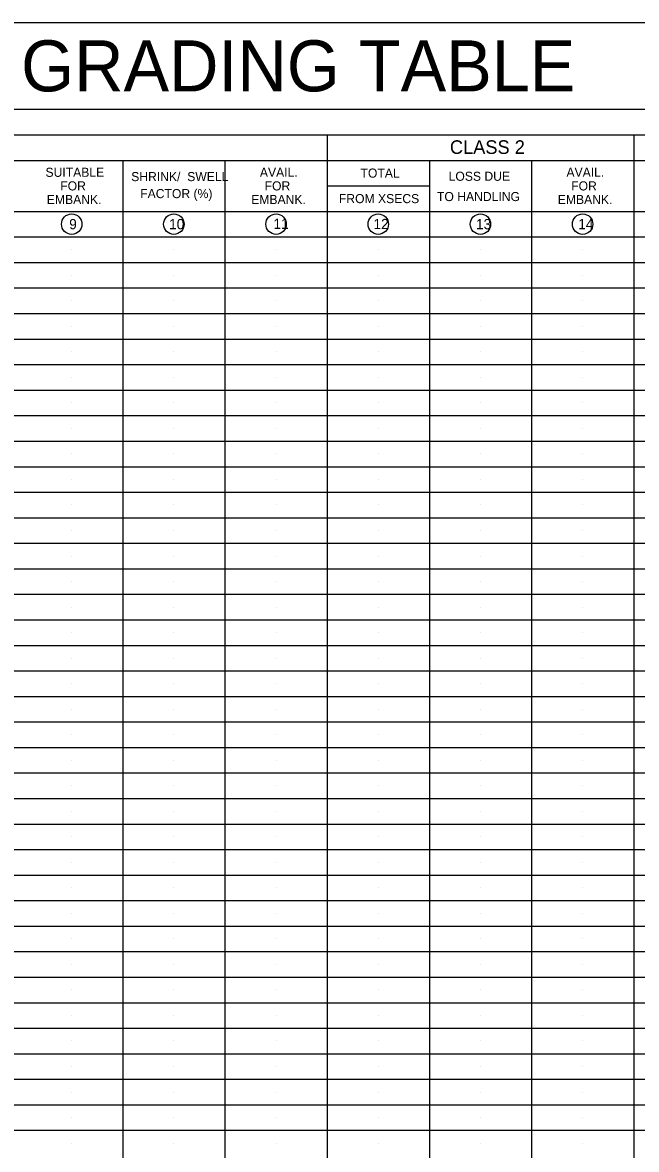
# Model space of a CAD drawing. Extents: x 1.3 to 38.6, y 0 to 21.1.
# Drawn here: x 9.92 to 15.32, y 11.12 to 21.05 of the extents above; entities that cross this region are included whole.
import ezdxf

# ---------------------------------------------------------------- set-up
doc = ezdxf.new("R2010")
doc.units = 0
for name, color, linetype in [('G-ANNO-TABL', 7, 'Continuous'), ('G-ANNO-TITL', 7, 'Continuous'), ('G-USER-LINE', 7, 'Continuous')]:
    doc.layers.add(name, color=color, linetype=linetype)

msp = doc.modelspace()

# ---------------------------------------------------------------- linework, layer by layer
at = {"layer": 'G-ANNO-TABL'}
for p, q in [((2.248, 21.055), (22.498, 21.055)), ((2.248, 20.29), (22.498, 20.29)), ((2.698, 20.065), (17.098, 20.065)), ((12.598, 20.0651), (12.598, 4.54)), ((15.298, 20.0651), (15.298, 4.54)), ((2.698, 19.84), (22.498, 19.84)), ((10.798, 19.8401), (10.798, 4.54)), ((11.698, 19.8401), (11.698, 4.54)), ((13.498, 19.8401), (13.498, 4.54)), ((14.398, 19.8401), (14.398, 4.54)), ((12.598, 19.615), (13.498, 19.615)), ((2.698, 19.39), (22.498, 19.39)), ((2.248, 19.165), (22.498, 19.165)), ((2.698, 18.94), (22.498, 18.94)), ((2.698, 18.715), (22.498, 18.715)), ((2.698, 18.49), (22.498, 18.49)), ((2.698, 18.265), (22.498, 18.265)), ((2.698, 18.04), (22.498, 18.04)), ((2.698, 17.815), (22.498, 17.815)), ((2.698, 17.59), (22.498, 17.59)), ((2.698, 17.365), (22.498, 17.365)), ((2.698, 17.14), (22.498, 17.14)), ((2.698, 16.915), (22.498, 16.915)), ((2.698, 16.69), (22.498, 16.69)), ((2.698, 16.465), (22.498, 16.465)), ((2.698, 16.24), (22.498, 16.24)), ((2.698, 16.015), (22.498, 16.015)), ((2.698, 15.79), (22.498, 15.79)), ((2.698, 15.565), (22.498, 15.565)), ((2.698, 15.34), (22.498, 15.34)), ((2.698, 15.115), (22.498, 15.115)), ((2.698, 14.89), (22.498, 14.89)), ((2.698, 14.665), (22.498, 14.665)), ((2.698, 14.44), (22.498, 14.44)), ((2.698, 14.215), (22.498, 14.215)), ((2.698, 13.99), (22.498, 13.99)), ((2.698, 13.765), (22.498, 13.765)), ((2.698, 13.54), (22.498, 13.54)), ((2.698, 13.315), (22.498, 13.315)), ((2.698, 13.09), (22.498, 13.09)), ((2.698, 12.865), (22.498, 12.865)), ((2.698, 12.64), (22.498, 12.64)), ((2.698, 12.415), (22.498, 12.415)), ((2.698, 12.19), (22.498, 12.19)), ((2.698, 11.965), (22.498, 11.965)), ((2.698, 11.74), (22.498, 11.74)), ((2.698, 11.515), (22.498, 11.515)), ((2.698, 11.29), (22.498, 11.29))]:
    msp.add_line(p, q, dxfattribs=at)
at = {"layer": 'G-ANNO-TITL'}
for centre in [(10.3479, 19.278), (11.2479, 19.278), (12.1479, 19.278), (13.0479, 19.278), (13.9479, 19.278), (14.8479, 19.278)]:
    msp.add_circle(centre, 0.09, dxfattribs=at)
at = {"layer": 'G-USER-LINE'}
for p, q in [((10.348, 19.2775), (10.348, 19.2775)), ((11.248, 19.2775), (11.248, 19.2775)), ((12.148, 19.2775), (12.148, 19.2775)), ((13.048, 19.2775), (13.048, 19.2775)), ((13.948, 19.2775), (13.948, 19.2775)), ((14.848, 19.2775), (14.848, 19.2775)), ((10.348, 19.0525), (10.348, 19.0525)), ((11.248, 19.0525), (11.248, 19.0525)), ((12.148, 19.0525), (12.148, 19.0525)), ((13.048, 19.0525), (13.048, 19.0525)), ((13.948, 19.0525), (13.948, 19.0525)), ((14.848, 19.0525), (14.848, 19.0525)), ((10.348, 18.8275), (10.348, 18.8275)), ((11.248, 18.8275), (11.248, 18.8275)), ((12.148, 18.8275), (12.148, 18.8275)), ((13.048, 18.8275), (13.048, 18.8275)), ((13.948, 18.8275), (13.948, 18.8275)), ((14.848, 18.8275), (14.848, 18.8275)), ((10.348, 18.6025), (10.348, 18.6025)), ((11.248, 18.6025), (11.248, 18.6025)), ((12.148, 18.6025), (12.148, 18.6025)), ((13.048, 18.6025), (13.048, 18.6025)), ((13.948, 18.6025), (13.948, 18.6025)), ((14.848, 18.6025), (14.848, 18.6025)), ((10.348, 18.3775), (10.348, 18.3775)), ((11.248, 18.3775), (11.248, 18.3775)), ((12.148, 18.3775), (12.148, 18.3775)), ((13.048, 18.3775), (13.048, 18.3775)), ((13.948, 18.3775), (13.948, 18.3775)), ((14.848, 18.3775), (14.848, 18.3775)), ((10.348, 18.1525), (10.348, 18.1525)), ((11.248, 18.1525), (11.248, 18.1525)), ((12.148, 18.1525), (12.148, 18.1525)), ((13.048, 18.1525), (13.048, 18.1525)), ((13.948, 18.1525), (13.948, 18.1525)), ((14.848, 18.1525), (14.848, 18.1525)), ((10.348, 17.9275), (10.348, 17.9275)), ((11.248, 17.9275), (11.248, 17.9275)), ((12.148, 17.9275), (12.148, 17.9275)), ((13.048, 17.9275), (13.048, 17.9275)), ((13.948, 17.9275), (13.948, 17.9275)), ((14.848, 17.9275), (14.848, 17.9275)), ((10.348, 17.7025), (10.348, 17.7025)), ((11.248, 17.7025), (11.248, 17.7025)), ((12.148, 17.7025), (12.148, 17.7025)), ((13.048, 17.7025), (13.048, 17.7025)), ((13.948, 17.7025), (13.948, 17.7025)), ((14.848, 17.7025), (14.848, 17.7025)), ((10.348, 17.4775), (10.348, 17.4775)), ((11.248, 17.4775), (11.248, 17.4775)), ((12.148, 17.4775), (12.148, 17.4775)), ((13.048, 17.4775), (13.048, 17.4775)), ((13.948, 17.4775), (13.948, 17.4775)), ((14.848, 17.4775), (14.848, 17.4775)), ((10.348, 17.2525), (10.348, 17.2525)), ((11.248, 17.2525), (11.248, 17.2525)), ((12.148, 17.2525), (12.148, 17.2525)), ((13.048, 17.2525), (13.048, 17.2525)), ((13.948, 17.2525), (13.948, 17.2525)), ((14.848, 17.2525), (14.848, 17.2525)), ((10.348, 17.0275), (10.348, 17.0275)), ((11.248, 17.0275), (11.248, 17.0275)), ((12.148, 17.0275), (12.148, 17.0275)), ((13.048, 17.0275), (13.048, 17.0275)), ((13.948, 17.0275), (13.948, 17.0275)), ((14.848, 17.0275), (14.848, 17.0275)), ((10.348, 16.8025), (10.348, 16.8025)), ((11.248, 16.8025), (11.248, 16.8025)), ((12.148, 16.8025), (12.148, 16.8025)), ((13.048, 16.8025), (13.048, 16.8025)), ((13.948, 16.8025), (13.948, 16.8025)), ((14.848, 16.8025), (14.848, 16.8025)), ((10.348, 16.5775), (10.348, 16.5775)), ((11.248, 16.5775), (11.248, 16.5775)), ((12.148, 16.5775), (12.148, 16.5775)), ((13.048, 16.5775), (13.048, 16.5775)), ((13.948, 16.5775), (13.948, 16.5775)), ((14.848, 16.5775), (14.848, 16.5775)), ((10.348, 16.3525), (10.348, 16.3525)), ((11.248, 16.3525), (11.248, 16.3525)), ((12.148, 16.3525), (12.148, 16.3525)), ((13.048, 16.3525), (13.048, 16.3525)), ((13.948, 16.3525), (13.948, 16.3525)), ((14.848, 16.3525), (14.848, 16.3525)), ((10.348, 16.1275), (10.348, 16.1275)), ((11.248, 16.1275), (11.248, 16.1275)), ((12.148, 16.1275), (12.148, 16.1275)), ((13.048, 16.1275), (13.048, 16.1275)), ((13.948, 16.1275), (13.948, 16.1275)), ((14.848, 16.1275), (14.848, 16.1275)), ((10.348, 15.9025), (10.348, 15.9025)), ((11.248, 15.9025), (11.248, 15.9025)), ((12.148, 15.9025), (12.148, 15.9025)), ((13.048, 15.9025), (13.048, 15.9025)), ((13.948, 15.9025), (13.948, 15.9025)), ((14.848, 15.9025), (14.848, 15.9025)), ((10.348, 15.6775), (10.348, 15.6775)), ((11.248, 15.6775), (11.248, 15.6775)), ((12.148, 15.6775), (12.148, 15.6775)), ((13.048, 15.6775), (13.048, 15.6775)), ((13.948, 15.6775), (13.948, 15.6775)), ((14.848, 15.6775), (14.848, 15.6775)), ((10.348, 15.4525), (10.348, 15.4525)), ((11.248, 15.4525), (11.248, 15.4525)), ((12.148, 15.4525), (12.148, 15.4525)), ((13.048, 15.4525), (13.048, 15.4525)), ((13.948, 15.4525), (13.948, 15.4525)), ((14.848, 15.4525), (14.848, 15.4525)), ((10.348, 15.2275), (10.348, 15.2275)), ((11.248, 15.2275), (11.248, 15.2275)), ((12.148, 15.2275), (12.148, 15.2275)), ((13.048, 15.2275), (13.048, 15.2275)), ((13.948, 15.2275), (13.948, 15.2275)), ((14.848, 15.2275), (14.848, 15.2275)), ((10.348, 15.0025), (10.348, 15.0025)), ((11.248, 15.0025), (11.248, 15.0025)), ((12.148, 15.0025), (12.148, 15.0025)), ((13.048, 15.0025), (13.048, 15.0025)), ((13.948, 15.0025), (13.948, 15.0025)), ((14.848, 15.0025), (14.848, 15.0025)), ((10.348, 14.7775), (10.348, 14.7775)), ((11.248, 14.7775), (11.248, 14.7775)), ((12.148, 14.7775), (12.148, 14.7775)), ((13.048, 14.7775), (13.048, 14.7775)), ((13.948, 14.7775), (13.948, 14.7775)), ((14.848, 14.7775), (14.848, 14.7775)), ((10.348, 14.5525), (10.348, 14.5525)), ((11.248, 14.5525), (11.248, 14.5525)), ((12.148, 14.5525), (12.148, 14.5525)), ((13.048, 14.5525), (13.048, 14.5525)), ((13.948, 14.5525), (13.948, 14.5525)), ((14.848, 14.5525), (14.848, 14.5525)), ((10.348, 14.3275), (10.348, 14.3275)), ((11.248, 14.3275), (11.248, 14.3275)), ((12.148, 14.3275), (12.148, 14.3275)), ((13.048, 14.3275), (13.048, 14.3275)), ((13.948, 14.3275), (13.948, 14.3275)), ((14.848, 14.3275), (14.848, 14.3275)), ((10.348, 14.1025), (10.348, 14.1025)), ((11.248, 14.1025), (11.248, 14.1025)), ((12.148, 14.1025), (12.148, 14.1025)), ((13.048, 14.1025), (13.048, 14.1025)), ((13.948, 14.1025), (13.948, 14.1025)), ((14.848, 14.1025), (14.848, 14.1025)), ((10.348, 13.8775), (10.348, 13.8775)), ((11.248, 13.8775), (11.248, 13.8775)), ((12.148, 13.8775), (12.148, 13.8775)), ((13.048, 13.8775), (13.048, 13.8775)), ((13.948, 13.8775), (13.948, 13.8775)), ((14.848, 13.8775), (14.848, 13.8775)), ((10.348, 13.6525), (10.348, 13.6525)), ((11.248, 13.6525), (11.248, 13.6525)), ((12.148, 13.6525), (12.148, 13.6525)), ((13.048, 13.6525), (13.048, 13.6525)), ((13.948, 13.6525), (13.948, 13.6525)), ((14.848, 13.6525), (14.848, 13.6525)), ((10.348, 13.4275), (10.348, 13.4275)), ((11.248, 13.4275), (11.248, 13.4275)), ((12.148, 13.4275), (12.148, 13.4275)), ((13.048, 13.4275), (13.048, 13.4275)), ((13.948, 13.4275), (13.948, 13.4275)), ((14.848, 13.4275), (14.848, 13.4275)), ((10.348, 13.2025), (10.348, 13.2025)), ((11.248, 13.2025), (11.248, 13.2025)), ((12.148, 13.2025), (12.148, 13.2025)), ((13.048, 13.2025), (13.048, 13.2025)), ((13.948, 13.2025), (13.948, 13.2025)), ((14.848, 13.2025), (14.848, 13.2025)), ((10.348, 12.9775), (10.348, 12.9775)), ((11.248, 12.9775), (11.248, 12.9775)), ((12.148, 12.9775), (12.148, 12.9775)), ((13.048, 12.9775), (13.048, 12.9775)), ((13.948, 12.9775), (13.948, 12.9775)), ((14.848, 12.9775), (14.848, 12.9775)), ((10.348, 12.7525), (10.348, 12.7525)), ((11.248, 12.7525), (11.248, 12.7525)), ((12.148, 12.7525), (12.148, 12.7525)), ((13.048, 12.7525), (13.048, 12.7525)), ((13.948, 12.7525), (13.948, 12.7525)), ((14.848, 12.7525), (14.848, 12.7525)), ((10.348, 12.5275), (10.348, 12.5275)), ((11.248, 12.5275), (11.248, 12.5275)), ((12.148, 12.5275), (12.148, 12.5275)), ((13.048, 12.5275), (13.048, 12.5275)), ((13.948, 12.5275), (13.948, 12.5275)), ((14.848, 12.5275), (14.848, 12.5275)), ((10.348, 12.3025), (10.348, 12.3025)), ((11.248, 12.3025), (11.248, 12.3025)), ((12.148, 12.3025), (12.148, 12.3025)), ((13.048, 12.3025), (13.048, 12.3025)), ((13.948, 12.3025), (13.948, 12.3025)), ((14.848, 12.3025), (14.848, 12.3025)), ((10.348, 12.0775), (10.348, 12.0775)), ((11.248, 12.0775), (11.248, 12.0775)), ((12.148, 12.0775), (12.148, 12.0775)), ((13.048, 12.0775), (13.048, 12.0775)), ((13.948, 12.0775), (13.948, 12.0775)), ((14.848, 12.0775), (14.848, 12.0775)), ((10.348, 11.8525), (10.348, 11.8525)), ((11.248, 11.8525), (11.248, 11.8525)), ((12.148, 11.8525), (12.148, 11.8525)), ((13.048, 11.8525), (13.048, 11.8525)), ((13.948, 11.8525), (13.948, 11.8525)), ((14.848, 11.8525), (14.848, 11.8525)), ((10.348, 11.6275), (10.348, 11.6275)), ((11.248, 11.6275), (11.248, 11.6275)), ((12.148, 11.6275), (12.148, 11.6275)), ((13.048, 11.6275), (13.048, 11.6275)), ((13.948, 11.6275), (13.948, 11.6275)), ((14.848, 11.6275), (14.848, 11.6275)), ((10.348, 11.4025), (10.348, 11.4025)), ((11.248, 11.4025), (11.248, 11.4025)), ((12.148, 11.4025), (12.148, 11.4025)), ((13.048, 11.4025), (13.048, 11.4025)), ((13.948, 11.4025), (13.948, 11.4025)), ((14.848, 11.4025), (14.848, 11.4025)), ((10.348, 11.1775), (10.348, 11.1775)), ((11.248, 11.1775), (11.248, 11.1775)), ((12.148, 11.1775), (12.148, 11.1775)), ((13.048, 11.1775), (13.048, 11.1775)), ((13.948, 11.1775), (13.948, 11.1775)), ((14.848, 11.1775), (14.848, 11.1775))]:
    msp.add_line(p, q, dxfattribs=at)

# ---------------------------------------------------------------- texts
at = {"layer": 'G-ANNO-TITL'}
for s, height, p in [('GRADING TABLE', 0.45, (9.902, 20.448)), ('CLASS 2', 0.12, (13.6789, 19.897)), ('SUITABLE', 0.08, (10.1171, 19.695)), ('AVAIL.', 0.08, (12.0054, 19.695)), ('TOTAL', 0.08, (12.8917, 19.688)), ('AVAIL.', 0.08, (14.7054, 19.695)), ('SHRINK/  SWELL', 0.08, (10.8719, 19.657)), ('LOSS DUE', 0.08, (13.6675, 19.66)), ('FOR', 0.08, (10.2472, 19.575)), ('FACTOR (%)', 0.08, (10.9515, 19.507)), ('FOR', 0.08, (12.0472, 19.575)), ('FOR', 0.08, (14.7472, 19.575)), ('EMBANK.', 0.08, (10.1289, 19.455)), ('EMBANK.', 0.08, (11.9289, 19.455)), ('FROM XSECS', 0.08, (12.7011, 19.463)), ('TO HANDLING', 0.08, (13.5652, 19.481)), ('EMBANK.', 0.08, (14.6289, 19.455)), ('9', 0.09, (10.326, 19.233)), ('10', 0.09, (11.206, 19.233)), ('11', 0.09, (12.125, 19.236)), ('12', 0.09, (13.006, 19.234)), ('13', 0.09, (13.909, 19.233)), ('14', 0.09, (14.809, 19.233))]:
    msp.add_text(s, height=height, dxfattribs=at).set_placement(p)

doc.saveas('drawing.dxf')
